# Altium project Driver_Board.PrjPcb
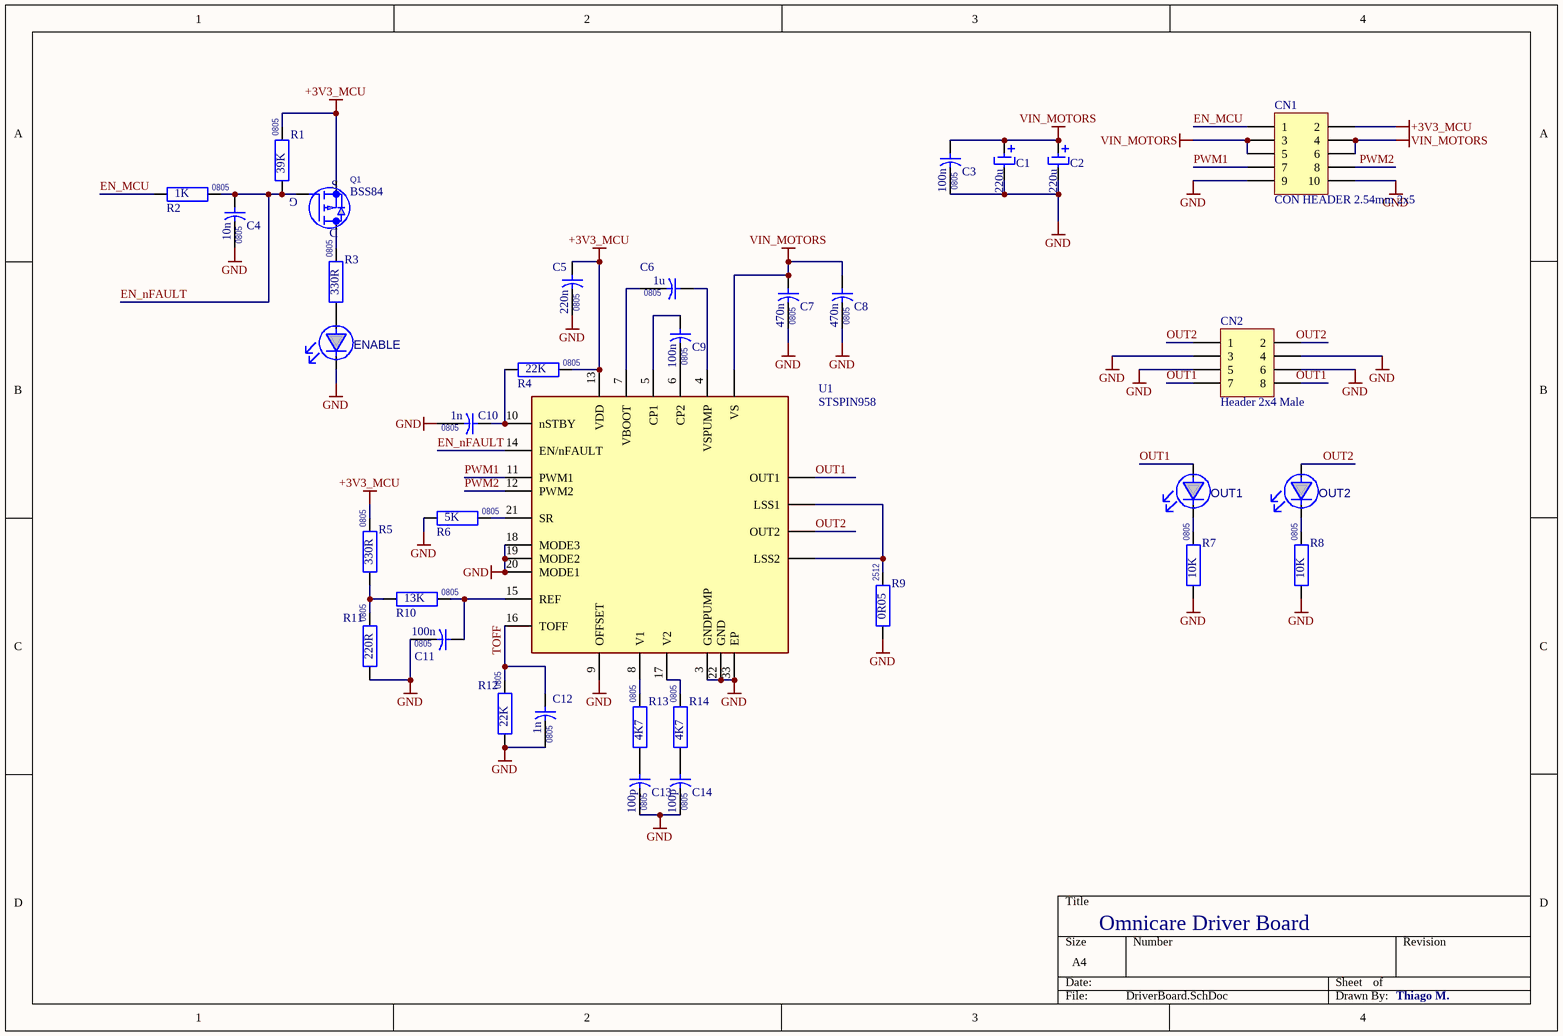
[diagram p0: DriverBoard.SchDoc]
1 sheet, 35 parts. Net scope: global (net labels, ports and power ports of the same name join across sheets).
Board file: DriverBoard_PCB.PcbDoc

## Sheet DriverBoard.SchDoc: Omnicare Driver Board
size A4; ApprovedBy: Thiago M.; CheckedBy: Thiago M.; Author: Thiago M.; CompanyName: Omnicare; DrawnBy: Thiago M.; SheetNumber: 1; SheetTotal: 1

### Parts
C1  220u  [CAP SMD ELE 10x10.2mm]
C2  220u  [CAP SMD ELE 10x10.2mm]
C3  100n  [CAP SMD CER 0805]
C4  10n  [CAP SMD CER 0805]
C5  220n  [CAP SMD CER 0805]
C6  1u  [CAP SMD CER 0805]
C7  470n  [CAP SMD CER 0805]
C8  470n  [CAP SMD CER 0805]
C9  100n  [CAP SMD CER 0805]
C10  1n  [CAP SMD CER 0805]
C11  100n  [CAP SMD CER 0805]
C12  1n  [CAP SMD CER 0805]
C13  100p  [CAP SMD CER 0805]
C14  100p  [CAP SMD CER 0805]
CN1  CON HEADER 2.54mm 2x5  [CON HEADER 2.54mm 2x5]
CN2  Header 2x4 Male  [Header 2x4 Male-Footprint-1]
ENABLE  RED  [LED SMD 0805]  (value not drawn)
OUT1  RED  [LED SMD 0805]  (value not drawn)
OUT2  RED  [LED SMD 0805]  (value not drawn)
Q1  BSS84  [SOT23]
R1  39K  [RES SMD 0805]
R2  1K  [RES SMD 0805]
R3  330R  [RES SMD 0805]
R4  22K  [RES SMD 0805]
R5  330R  [RES SMD 0805]
R6  5K  [RES SMD 0805]
R7  10K  [RES SMD 0805]
R8  10K  [RES SMD 0805]
R9  0R05  [RES SMD 2512]
R10  13K  [RES SMD 0805]
R11  220R  [RES SMD 0805]
R12  22K  [RES SMD 0805]
R13  4K7  [RES SMD 0805]
R14  4K7  [RES SMD 0805]
U1  STSPIN958  [NBG32 (VFQFPN 32)]

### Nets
+3V3_MCU: C5.1 CN1.2 Q1.2(S) R1.1 R4.1 R5.1 U1.13(VDD)
GND: C1.2 C2.2 C3.2 C4.2 C5.2 C7.2 C8.2 C10.2 C11.2 C12.2 C13.2 C14.2 CN1.9 CN1.10 CN2.3 CN2.4 CN2.5 CN2.6 ENABLE.2(K) R6.2 R7.2 R8.2 R9.2 R11.2 R12.2 U1.3(GNDPUMP) U1.9(OFFSET) U1.18(MODE3) U1.19(MODE2) U1.20(MODE1) U1.22(GND) U1.33(EP)
VIN_MOTORS: C1.1 C2.1 C3.1 C7.1 C8.1 CN1.3 CN1.4 CN1.5 CN1.6 U1.27,_28,_29,_30(VS)
EN_MCU: CN1.1 R2.2
EN_nFAULT: C4.1 Q1.1(G) R1.2 R2.1 U1.14(EN/nFAULT)
OUT1: CN2.7 CN2.8 OUT1.1(A) U1.31,_32(OUT1)
OUT2: CN2.1 CN2.2 OUT2.1(A) U1.25,_26(OUT2)
PWM1: CN1.7 U1.11(PWM1)
PWM2: CN1.8 U1.12(PWM2)
TOFF: C12.1 R12.1 U1.16(TOFF)
NetC6_1: C6.1 U1.4(VSPUMP)
NetC6_2: C6.2 U1.7(VBOOT)
NetC9_1: C9.1 U1.5(CP1)
NetC9_2: C9.2 U1.6(CP2)
NetC10_1: C10.1 R4.2 U1.10(nSTBY)
NetC11_1: C11.1 R10.1 U1.15(REF)
NetC13_1: C13.1 R13.2
NetC14_1: C14.1 R14.2
NetENABLE_1: ENABLE.1(A) R3.2
NetOUT1_2: OUT1.2(K) R7.1
NetOUT2_2: OUT2.2(K) R8.1
NetQ1_3: Q1.3(D) R3.1
NetR5_2: R5.2 R10.2 R11.1
NetR6_1: R6.1 U1.21(SR)
NetR9_1: R9.1 U1.1,_2(LSS1) U1.23,_24(LSS2)
NetR13_1: R13.1 U1.8(V1)
NetR14_1: R14.1 U1.17(V2)

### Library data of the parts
C1 C2 = CAP SMD - Gen. Electrolytic: Generic electrolytic capacitors for general purpose.
C3-C14 = CAP SMD - Gen. Ceramic 0805: Generic ceramic capacitor with package 0805 for general purpose.
CN2 = CMP-00003-1: Pin Header  2x4 Male 2.54mm
ENABLE OUT1 OUT2 = LED SMD - Gen. 0805: LED - SMD - 0805; PN: NCD0805R1
Q1 = BSS84: TRANSISTOR - Mosfet  P Channel - 130 mA - 50VDS - 20VGS - SOT23; Vds: -50V; Vgso: -+20V; Vth: -0.8V to -2V; Id: -130 mA
R1-R8 R10-R14 = RES SMD - Gen. 0805: Generic resistor with package 0805 for general purpose
R9 = RES SMD - Gen. 2512: Generic resistor with package 2512 for general purpose
U1 = STSPIN958: ST Motor driver up to 58V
